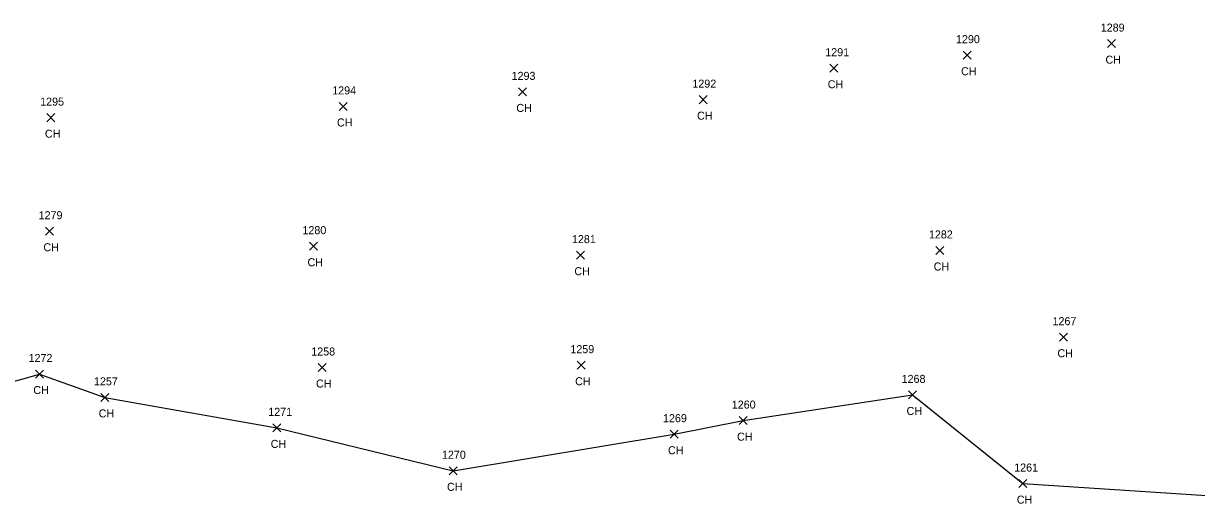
# Model space of a CAD drawing. Extents: x 1716490 to 1717645, y 888034 to 890004.
# Drawn here: x 1717066.5 to 1717358.9, y 888067 to 888187.5 of the extents above; entities that cross this region are included whole.
import ezdxf

# ---------------------------------------------------------------- set-up
doc = ezdxf.new("R2010")
doc.units = 0
for name, color, linetype in [('L_A', 7, 'Continuous'), ('L_I', 7, 'Continuous'), ('L_TIC', 7, 'Continuous'), ('LSOGP', 7, 'Continuous')]:
    doc.layers.add(name, color=color, linetype=linetype)

msp = doc.modelspace()

# ---------------------------------------------------------------- linework, layer by layer
at = {"layer": 'L_TIC'}
for points in [[(1717336.74, 888181.47), (1717338.74, 888183.47)], [(1717338.74, 888181.47), (1717336.74, 888183.47)], [(1717300.74, 888178.58), (1717302.74, 888180.58)], [(1717302.74, 888178.58), (1717300.74, 888180.58)], [(1717267.5, 888175.33), (1717269.5, 888177.33)], [(1717269.5, 888175.33), (1717267.5, 888177.33)], [(1717189.89, 888169.43), (1717191.89, 888171.43)], [(1717191.89, 888169.43), (1717189.89, 888171.43)], [(1717145.17, 888165.8), (1717147.17, 888167.8)], [(1717147.17, 888165.8), (1717145.17, 888167.8)], [(1717234.95, 888167.49), (1717236.95, 888169.49)], [(1717236.95, 888167.49), (1717234.95, 888169.49)], [(1717072.37, 888163), (1717074.37, 888165)], [(1717074.37, 888163), (1717072.37, 888165)], [(1717072, 888134.68), (1717074, 888136.68)], [(1717074, 888134.68), (1717072, 888136.68)], [(1717137.83, 888130.94), (1717139.83, 888132.94)], [(1717139.83, 888130.94), (1717137.83, 888132.94)], [(1717293.9, 888129.88), (1717295.9, 888131.88)], [(1717295.9, 888129.88), (1717293.9, 888131.88)], [(1717204.36, 888128.71), (1717206.36, 888130.71)], [(1717206.36, 888128.71), (1717204.36, 888130.71)], [(1717324.76, 888108.24), (1717326.76, 888110.24)], [(1717326.76, 888108.24), (1717324.76, 888110.24)], [(1717139.96, 888100.68), (1717141.96, 888102.68)], [(1717141.96, 888100.68), (1717139.96, 888102.68)], [(1717204.54, 888101.26), (1717206.54, 888103.26)], [(1717206.54, 888101.26), (1717204.54, 888103.26)], [(1717069.48, 888099.06), (1717071.48, 888101.06)], [(1717071.48, 888099.06), (1717069.48, 888101.06)], [(1717085.78, 888093.24), (1717087.78, 888095.24)], [(1717087.78, 888093.24), (1717085.78, 888095.24)], [(1717287.15, 888093.85), (1717289.15, 888095.85)], [(1717289.15, 888093.85), (1717287.15, 888095.85)], [(1717244.9, 888087.44), (1717246.9, 888089.44)], [(1717246.9, 888087.44), (1717244.9, 888089.44)], [(1717128.67, 888085.63), (1717130.67, 888087.63)], [(1717130.67, 888085.63), (1717128.67, 888087.63)], [(1717227.68, 888084.05), (1717229.68, 888086.05)], [(1717229.68, 888084.05), (1717227.68, 888086.05)], [(1717172.6, 888074.93), (1717174.6, 888076.93)], [(1717174.6, 888074.93), (1717172.6, 888076.93)], [(1717314.64, 888071.73), (1717316.64, 888073.73)], [(1717316.64, 888071.73), (1717314.64, 888073.73)]]:
    msp.add_lwpolyline(points, dxfattribs=at)
at = {"layer": 'LSOGP'}
msp.add_lwpolyline([(1717021.98, 888086.34), (1717070.48, 888100.06), (1717086.78, 888094.24), (1717129.67, 888086.63), (1717173.6, 888075.93), (1717228.68, 888085.05), (1717245.9, 888088.44), (1717288.15, 888094.85), (1717315.64, 888072.73), (1717403.35, 888067.01)], dxfattribs=at)

# ---------------------------------------------------------------- texts
at = {"layer": 'L_A'}
for p in [(1717336.23, 888177.47), (1717300.23, 888174.58), (1717266.99, 888171.33), (1717189.38, 888165.43), (1717234.43, 888163.49), (1717144.66, 888161.8), (1717071.86, 888159), (1717071.49, 888130.68), (1717137.32, 888126.94), (1717203.85, 888124.71), (1717293.39, 888125.88), (1717324.25, 888104.24), (1717068.97, 888095.06), (1717139.44, 888096.68), (1717204.03, 888097.26), (1717085.27, 888089.24), (1717286.64, 888089.85), (1717244.39, 888083.44), (1717128.15, 888081.63), (1717227.17, 888080.05), (1717172.09, 888070.93), (1717314.13, 888067.73)]:
    msp.add_text('CH', height=2, dxfattribs=at).set_placement(p)
at = {"layer": 'L_I'}
for s, p in [('1289', (1717335.04, 888185.47)), ('1290', (1717298.96, 888182.58)), ('1291', (1717266.38, 888179.33)), ('1293', (1717188.19, 888173.43)), ('1292', (1717233.25, 888171.49)), ('1294', (1717143.48, 888169.8)), ('1295', (1717070.68, 888167)), ('1279', (1717070.3, 888138.68)), ('1280', (1717136.05, 888134.94)), ('1281', (1717203.23, 888132.71)), ('1282', (1717292.21, 888133.88)), ('1267', (1717323.02, 888112.24)), ('1258', (1717138.26, 888104.68)), ('1259', (1717202.84, 888105.26)), ('1272', (1717067.79, 888103.06)), ('1268', (1717285.41, 888097.85)), ('1257', (1717084.09, 888097.24)), ('1271', (1717127.54, 888089.63)), ('1260', (1717243.07, 888091.44)), ('1269', (1717225.93, 888088.05)), ('1270', (1717170.82, 888078.93)), ('1261', (1717313.47, 888075.73))]:
    msp.add_text(s, height=2, dxfattribs=at).set_placement(p)

doc.saveas('drawing.dxf')
